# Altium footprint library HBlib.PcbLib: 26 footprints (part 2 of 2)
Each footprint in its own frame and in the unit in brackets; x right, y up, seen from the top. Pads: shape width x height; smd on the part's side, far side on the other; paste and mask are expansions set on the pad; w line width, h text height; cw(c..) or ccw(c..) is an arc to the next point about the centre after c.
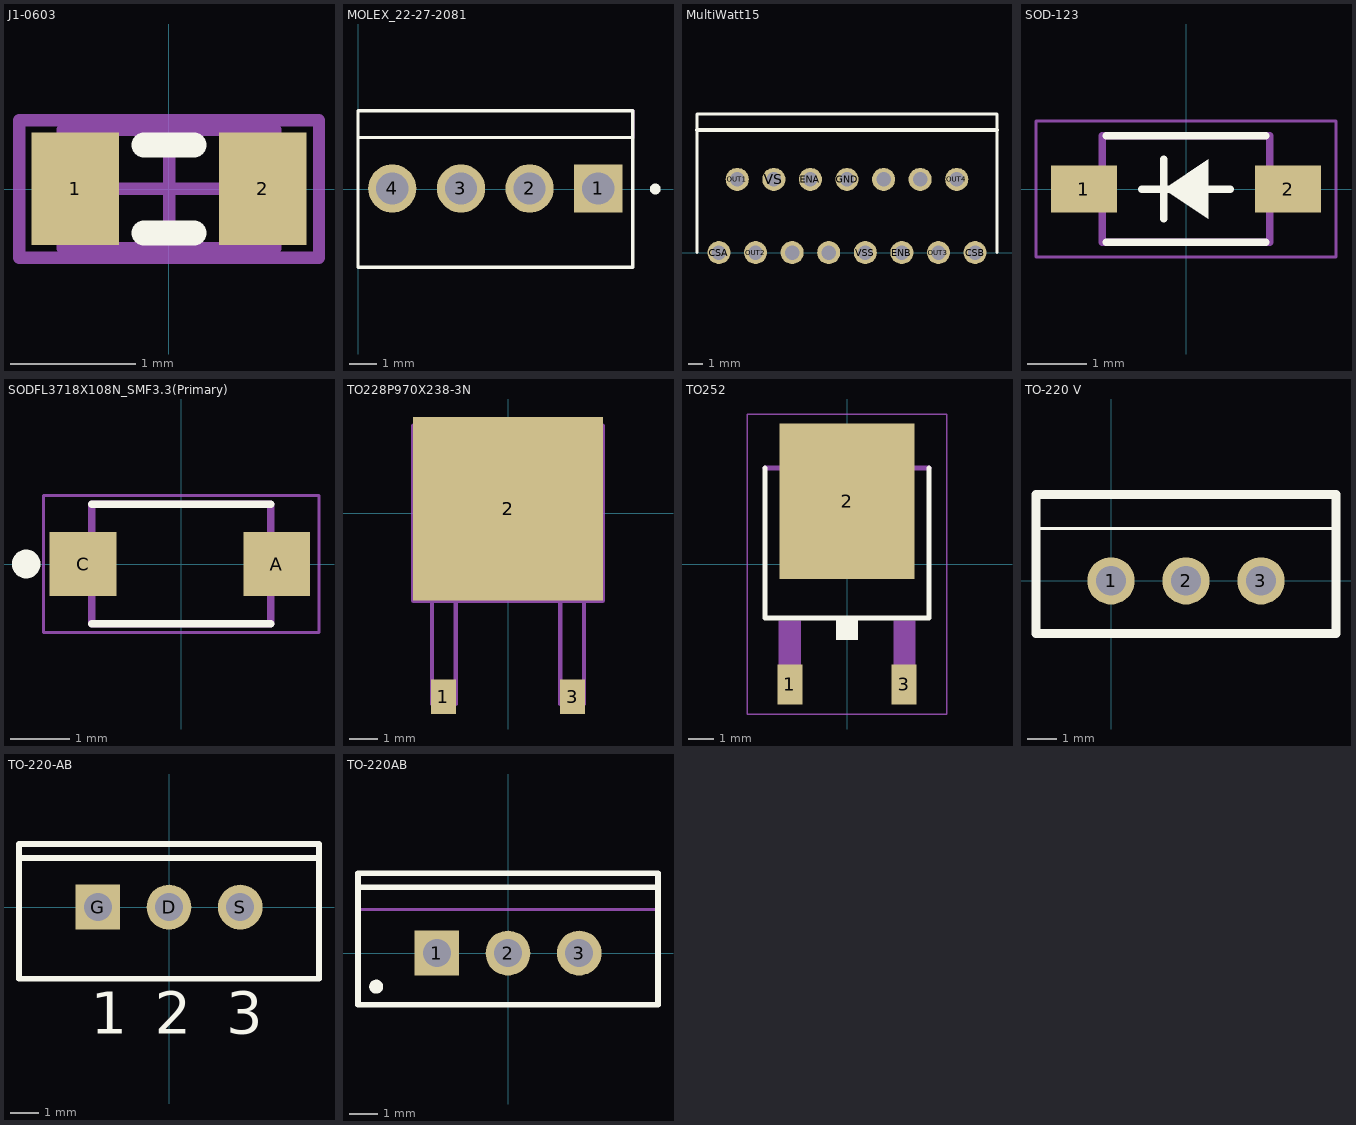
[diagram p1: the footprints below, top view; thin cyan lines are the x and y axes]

## J1-0603 [mm] "Chip Resistor, Body 1.6x0.8mm, IPC High Density"
height 0.9
pads (2):
  rect 0.7x0.9 smd: 1(-0.75,0) 2(0.75,0)
Top Overlay:
  lines w0.2: -0.2,-0.35 0.2,-0.35 ; -0.2,0.35 0.2,0.35
Mechanical 13:
  lines w0.1: -0.85,-0.475 0.85,-0.475 0.85,0.475 -0.85,0.475 -0.85,-0.475
Mechanical 15:
  lines w0.1: -0.475,0 0.475,0 ; 0,-0.475 0,0.475 ; -1.2,-0.55 1.2,-0.55 1.2,0.55 -1.2,0.55 -1.2,-0.55
3D body: height 0.9, standoff 0, extent -0.85,-0.475 0.85,0.475

## MOLEX_22-27-2081 [mm]
pads (4):
  rect 1.785x1.785 hole 1.19: 1(8.89,0.02)
  round 1.785 hole 1.19: 2(6.35,0.02) 3(3.81,0.02) 4(1.27,0.02)
Top Overlay:
  circle w0.2: c11,0 r0.1
  lines w0.127: 0,1.905 10.16,1.905 ; 0,-2.9 10.16,-2.9 10.16,2.9 0,2.9 0,-2.9
Mechanical 4:
  circle w0.2: c8.89,0 r0.1
  circle w0.2: c8.89,0 r0.1
  lines w0.127: 10.16,1.9 10.16,2.9

## MultiWatt15 [mm] "MultiWatt15; 15 Leads; Row Spacing 5.08 mm; Pitch 2.54 mm"
height 5.08
pads (15):
  round 1.6 hole 1: CSA(4.064,0) CSB(21.844,0) ENA(10.414,5.08) ENB(16.764,0) GND(12.954,5.08) input1(9.144,0) input2(11.684,0) input3(15.494,5.08) input4(18.034,5.08) OUT1(5.334,5.08) OUT2(6.604,0) OUT3(19.304,0) OUT4(20.574,5.08) VS(7.874,5.08) VSS(14.224,0)
Top Overlay:
  lines w0.2: 2.54,0 2.54,9.627 23.368,9.627 23.368,0
  lines w0.254: 2.54,8.509 23.368,8.509

## SOD-123 [mm]
pads (2):
  rect 1.12x0.8 smd: 1(-1.73,0) 2(1.73,0)
Top Overlay:
  region: -0.375,0 0.375,0.5 0.375,-0.5
  lines w0.127: -1.35,-0.9 1.35,-0.9 ; -1.35,0.9 1.35,0.9 ; -0.75,0 0.75,0 ; -0.375,-0.5 -0.375,0.5
Mechanical 4:
  lines w0.127: -1.42,-0.9 -1.42,0.9 ; -1.42,-0.9 1.42,-0.9 ; -1.42,-0.9 -1.42,0.9 ; -1.42,-0.9 1.42,-0.9 ; -1.42,0.9 1.42,0.9 ; -1.42,0.9 1.42,0.9 ; 1.42,-0.9 1.42,0.9 ; 1.42,-0.9 1.42,0.9
Mechanical 16:
  lines w0.05: -2.54,-1.15 2.54,-1.15 2.54,1.15 -2.54,1.15 -2.54,-1.15

## SODFL3718X108N_SMF3.3(Primary) [mm]
pads (2):
  rect 1.12x1.08 smd: A(1.6,0) C(-1.645,0)
Top Overlay:
  circle w0.24: c-2.6,0 r0.12
  lines w0.127: -1.5,-1 1.5,-1 ; -1.5,1 1.5,1
Mechanical 4:
  lines w0.127: -1.5,-1 -1.5,1 ; -1.5,-1 1.5,-1 ; -1.5,-1 -1.5,1 ; -1.5,-1 1.5,-1 ; -1.5,1 1.5,1 ; -1.5,1 1.5,1 ; 1.5,-1 1.5,1 ; 1.5,-1 1.5,1
Mechanical 16:
  lines w0.05: -2.31,-1.15 -2.31,1.15 2.31,1.15 2.31,-1.15 -2.31,-1.15

## TO228P970X238-3N [mil]
pads (3):
  rect 35x48 smd: 1(-90,-256) 3(90,-256)
  rect 265x256 smd: 2(0,6)
Mechanical 4:
  lines w6: -132,-122 132,-122 ; -132,-122 -132,122 ; -132,-122 132,-122 ; -132,-122 -132,122 ; -132,122 132,122 ; -132,122 132,122 ; -106,-266 -106,-122 ; -106,-266 -73,-266 ; -106,-266 -106,-122 ; -106,-266 -73,-266 ; -106,-122 -73,-122 ; -106,-122 -73,-122 ; -73,-266 -73,-122 ; -73,-266 -73,-122 ; 73,-266 73,-122 ; 73,-266 106,-266 ; 73,-266 73,-122 ; 73,-266 106,-266 ; 73,-122 106,-122 ; 73,-122 106,-122 ; 106,-266 106,-122 ; 106,-266 106,-122 ; 132,-122 132,122 ; 132,-122 132,122

## TO252 [mm]
pads (3):
  rect 1x1.6 smd: 1(-2.28,-4.8) 3(2.28,-4.8)
  rect 5.4x6.2 smd: 2(0,2.5)
Top Overlay:
  region: -0.432,-2.261 0.432,-2.261 0.432,-3.025 -0.432,-3.025
  lines w0.203: -3.277,3.835 -3.277,-2.159 3.277,-2.159 3.277,3.835
Mechanical 4:
  region: -2.565,3.937 -2.565,4.648 -2.108,5.105 2.108,5.105 2.565,4.648 2.565,3.937
  region: 1.858,-2.261 2.718,-2.261 2.718,-5.166 1.858,-5.166
  region: -2.719,-2.261 -1.854,-2.261 -1.854,-5.159 -2.719,-5.159
  region: -2.565,3.937 -2.565,4.648 -2.108,5.105 2.108,5.105 2.565,4.648 2.565,3.937
  region: 1.858,-2.261 2.718,-2.261 2.718,-5.166 1.858,-5.166
  region: -2.719,-2.261 -1.854,-2.261 -1.854,-5.159 -2.719,-5.159
  lines w0.203: -2.565,3.937 2.565,3.937 ; -2.565,3.937 -2.565,4.648 ; -2.565,3.937 2.565,3.937 ; -2.565,3.937 -2.565,4.648 ; -2.565,4.648 -2.108,5.105 ; -2.565,4.648 -2.108,5.105 ; -2.108,5.105 2.108,5.105 ; -2.108,5.105 2.108,5.105 ; 2.108,5.105 2.565,4.648 ; 2.108,5.105 2.565,4.648 ; 2.565,3.937 2.565,4.648 ; 2.565,3.937 2.565,4.648 ; -3.277,3.835 3.277,3.835 -3.277,3.835
Mechanical 16:
  lines w0.051: -3.973,-5.983 -3.973,5.983 3.973,5.983 3.973,-5.983 -3.973,-5.983

## TO-220 V [mm] "TO-220 Vertical"
height 20
pads (3):
  round 1.6 hole 1: 1(0,0) 2(2.54,0) 3(5.08,0)
Top Overlay:
  lines w0.102: -2.54,1.778 7.62,1.778
  lines w0.305: -2.54,-1.778 7.62,-1.778 7.62,1.778 7.62,2.921 -2.54,2.921 -2.54,1.778 -2.54,-1.778

## TO-220-AB [mm] "TO, Thru-Hole, Vertical, Heatsink Mounted; 3 In-Line Leads; Pitch 2.54 mm"
height 19.1
pads (3):
  round 1.6 hole 1: D(0,0) S(2.54,0)
  rect 1.6x1.6 hole 1: G(-2.54,0)
Top Overlay:
  lines w0.2: -5.35,1.75 5.35,1.75 ; -5.35,-2.55 5.35,-2.55 5.35,2.25 -5.35,2.25 -5.35,-2.55
  text "1" at -2.79,-4.525 h1.5
  text "2" at -0.5,-4.525 h1.5
  text "3" at 2.04,-4.525 h1.5

## TO-220AB [mm] "TO, Thru-Hole, Vertical, Heatsink Mounted; 3 In-Line Leads; Pitch 2.54 mm"
height 19.3
pads (3):
  rect 1.6x1.6 hole 1: 1(-2.54,0)
  round 1.6 hole 1: 2(0,0) 3(2.54,0)
Top Overlay:
  circle w0.25: c-4.7,-1.2 r0.125
  lines w0.2: -5.35,2.35 5.35,2.35 ; -5.35,-1.85 -5.35,2.85 5.35,2.85 5.35,-1.85 -5.35,-1.85
Mechanical 13:
  lines w0.1: -5.35,1.55 5.35,1.55 ; -5.35,-1.85 5.35,-1.85 5.35,2.85 -5.35,2.85 -5.35,-1.85
Mechanical 15:
  lines w0.1: -0.5,0 0.5,0 ; 0,-0.5 0,0.5
3D body: height 12.9, standoff 4, extent -5.4,-1.9 5.4,2.9
3D body: height 19.3, standoff 12.9, extent -5.349,1.551 5.349,2.849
